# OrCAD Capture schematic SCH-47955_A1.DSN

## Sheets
1 01_TITLE: title: OM29110BBB-B; rev: A1; note: SCH-47955 PDF: SPF-47955
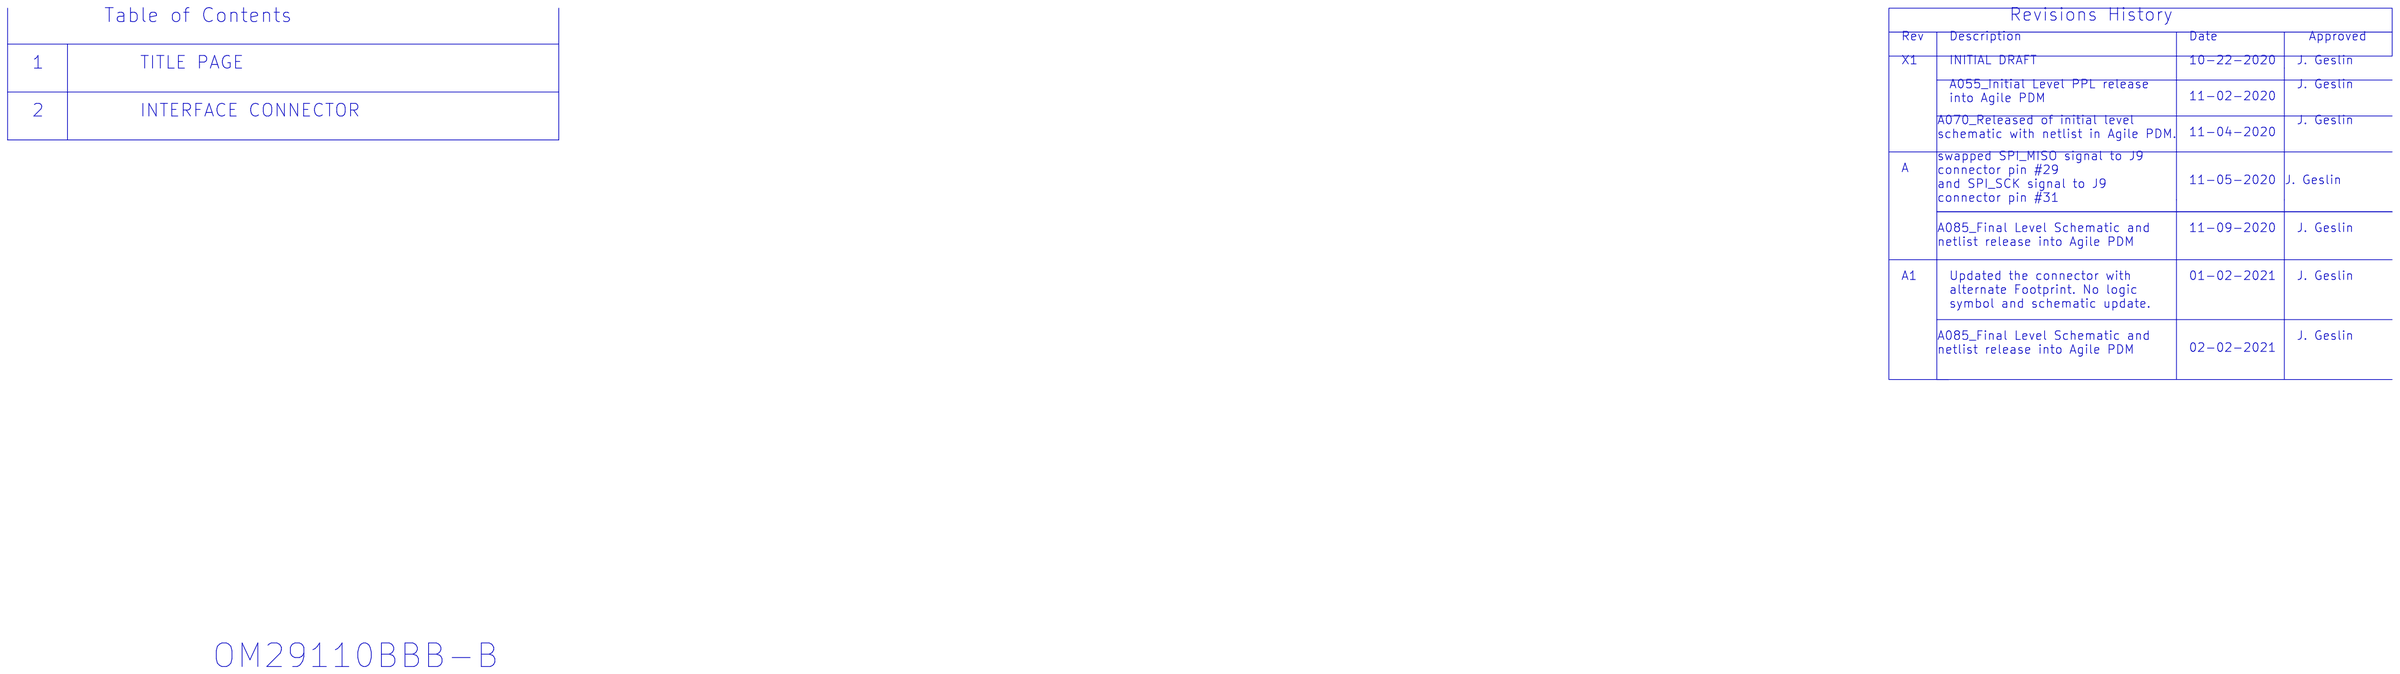
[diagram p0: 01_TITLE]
2 02_INTERFACE CONNECTORS: size C; company: NXP Semiconductors; note: 6501 William Cannon Drive West; note: Austin, TX 78735-8598
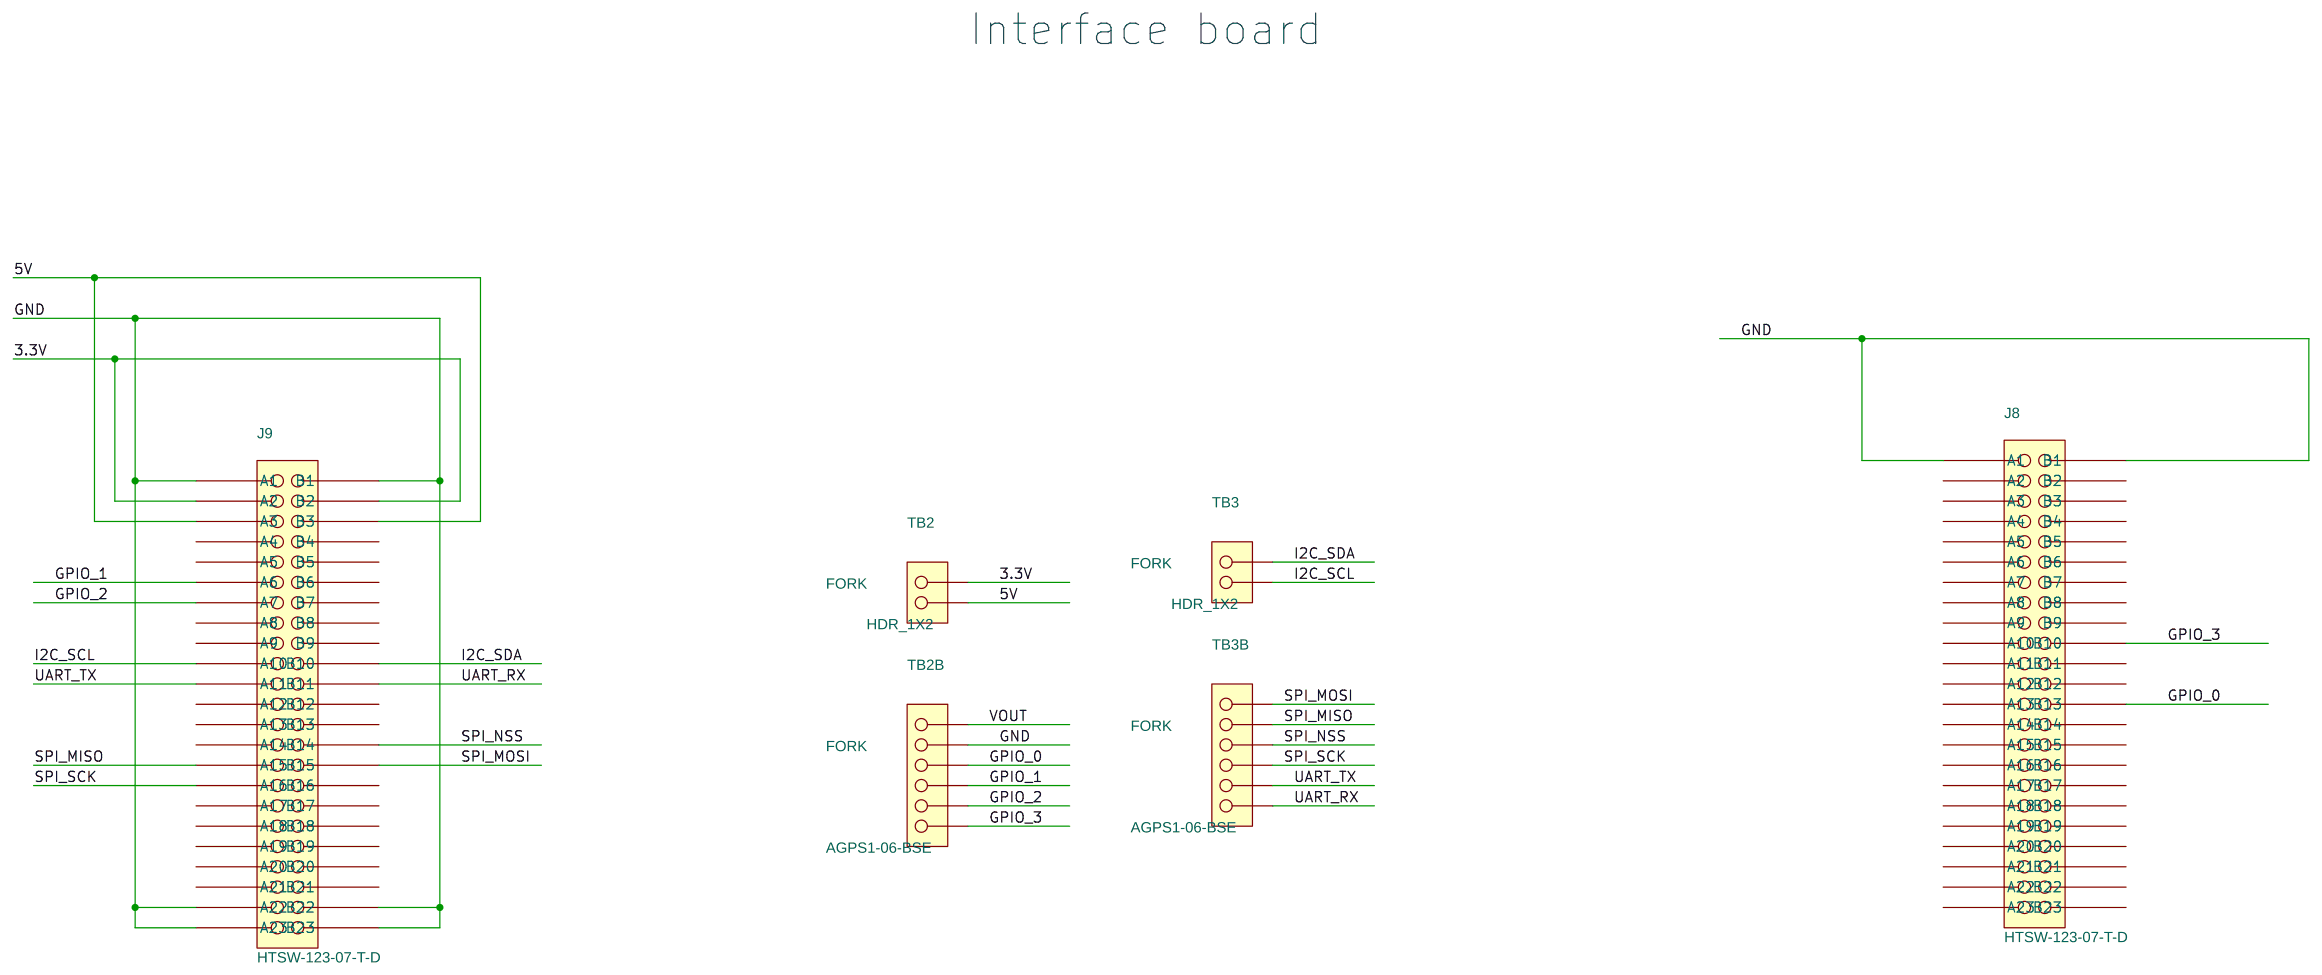
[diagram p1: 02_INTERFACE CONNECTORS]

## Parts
J8  HTSW-123-07-T-D  [hdr2x23_100_th_nsp]
J9  HTSW-123-07-T-D  [hdr2x23_100_th_nsp]
TB2  HDR_1X2  [skt1x2_2p54_th_bse]
TB2B  AGPS1-06-BSE  [skt1x6_2p54_th_bse]
TB3  HDR_1X2  [skt1x2_2p54_th_bse]
TB3B  AGPS1-06-BSE  [skt1x6_2p54_th_bse]

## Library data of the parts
J8 J9 = CONN_HDR_23X2: HDR 2X23 TH 100 MIL CTR 340H SN 100L; AGILE_PN: 210-81714; CAD_APPROVED: Yes; FPLIST: HDR2X23_100_TH,hdr2x23_100_th_nsp; HEIGHT: 8.63MM; MFG_NAME01: SAMTEC; ROHS: Yes; Temp Range: -55°C to +105°C
TB2 TB3 = CONN_HDR_2X1: CON 1X2 SKT TH 100MIL SP 276H SN 196L; AGILE_PN: 210-82543; CAD_APPROVED: Yes; Contact Voltage: 1000Vrms; HEIGHT: 7.0MM; MFG_NAME01: ANTELEC; MFG_PN01: AGPS1-02-BSE-1MM3; Package Size: 5.08 x2.5mm; Package Type: CON HDR TH; ROHS: Yes; SILK: FORK; Temp Range: -55C to +125C
TB2B TB3B = CONN_HDR_6X1: CON 1X6 TB TH 100MIL 276H SN 196L; AGILE_PN: 210-81709; CAD_APPROVED: Yes; HEIGHT: 7MM; MFG_NAME01: ANTELEC; ROHS: Yes; SILK: FORK; Temp Range: -55°C ~ 125°C

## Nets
3.3V: J9.3(A2) J9.4(B2) TB2.1
5V: J9.5(A3) J9.6(B3) TB2.2
GND: J8.1(A1) J8.2(B1) J9.1(A1) J9.2(B1) J9.43(A22) J9.44(B22) J9.45(A23) J9.46(B23) TB2B.2
GPIO_0: J8.26(B13) TB2B.3
GPIO_1: J9.11(A6) TB2B.4
GPIO_2: J9.13(A7) TB2B.5
GPIO_3: J8.20(B10) TB2B.6
I2C_SCL: J9.19(A10) TB3.2
I2C_SDA: J9.20(B10) TB3.1
SPI_MISO: J9.29(A15) TB3B.2
SPI_MOSI: J9.30(B15) TB3B.1
SPI_NSS: J9.28(B14) TB3B.3
SPI_SCK: J9.31(A16) TB3B.4
UART_RX: J9.22(B11) TB3B.6
UART_TX: J9.21(A11) TB3B.5
VOUT: TB2B.1

Not connected (* = marked no-connect by the designer): J8 3(A2) 4(B2) 5(A3) 6(B3) 7(A4) 8(B4) 9(A5) 10(B5) 11(A6) 12(B6) 13(A7) 14(B7) 15(A8) 16(B8) 17(A9) 18(B9) 19(A10) 21(A11) 22(B11) 23(A12) 24(B12) 25(A13) 27(A14) 28(B14) 29(A15) 30(B15) 31(A16) 32(B16) 33(A17) 34(B17) 35(A18) 36(B18) 37(A19) 38(B19) 39(A20) 40(B20) 41(A21) 42(B21) 43(A22) 44(B22) 45(A23) 46(B23); J9 7(A4) 8(B4) 9(A5) 10(B5) 12(B6) 14(B7) 15(A8) 16(B8) 17(A9) 18(B9) 23(A12) 24(B12) 25(A13) 26(B13) 27(A14) 32(B16) 33(A17) 34(B17) 35(A18) 36(B18) 37(A19) 38(B19) 39(A20) 40(B20) 41(A21) 42(B21)

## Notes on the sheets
sheet 1
- Table of Contents
- Revisions History
- Rev
- Description
- Date
- Approved
- 1
- TITLE PAGE
- X1
- INITIAL DRAFT
- 10-22-2020
- J. Geslin
- A055_Initial Level PPL release
  into Agile PDM
- J. Geslin
- 11-02-2020
- 2
- INTERFACE CONNECTOR
- A070_Released of initial level
  schematic with netlist in Agile PDM.
- J. Geslin
- 11-04-2020
- swapped SPI_MISO signal to J9
  connector pin #29
  and SPI_SCK signal to J9
  connector pin #31
- A
- 11-05-2020
- J. Geslin
- A085_Final Level Schematic and
  netlist release into Agile PDM
- 11-09-2020
- J. Geslin
- A1
- Updated the connector with
  alternate Footprint. No logic
  symbol and schematic update.
- 01-02-2021
- J. Geslin
- A085_Final Level Schematic and
  netlist release into Agile PDM
- J. Geslin
- 02-02-2021
- OM29110BBB-B
sheet 2
- Interface board
